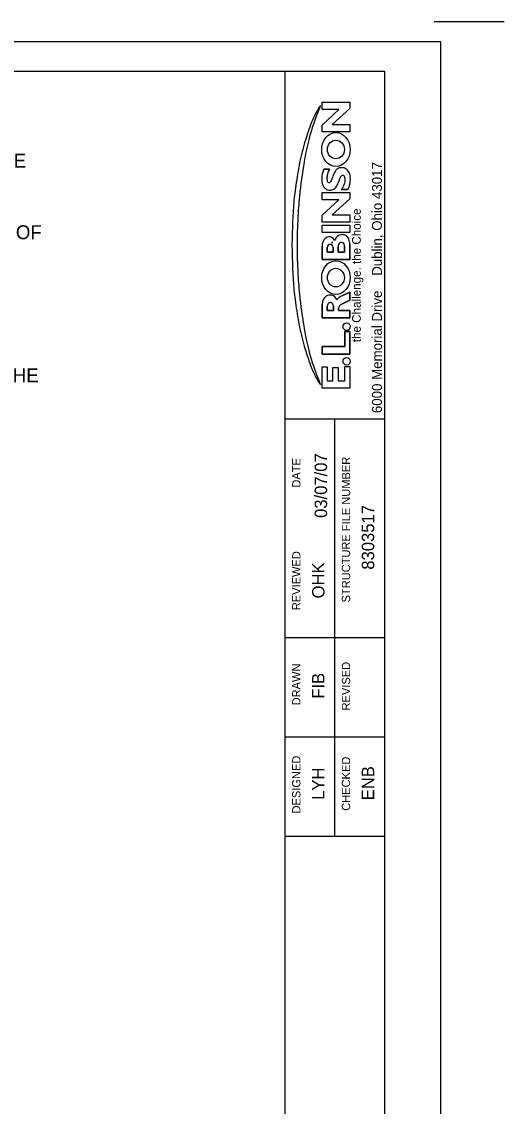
# Model space of a CAD drawing. Extents: x -70.8 to -34.9, y -11.3 to 10.7.
# Drawn here: x -39.72 to -34.87, y -0.19 to 10.73 of the extents above; entities that cross this region are included whole.
import ezdxf

# ---------------------------------------------------------------- set-up
doc = ezdxf.new("R2010")
doc.units = 0
for name, color, linetype in [('BR_P_Gen_Text', 7, 'Continuous'), ('Default', 7, 'Continuous'), ('SH_Border', 7, 'Continuous'), ('SH_Cut_Line', 7, 'Continuous'), ('SH_Data', 7, 'Continuous')]:
    doc.layers.add(name, color=color, linetype=linetype)

msp = doc.modelspace()

# ---------------------------------------------------------------- linework, layer by layer
at = {"layer": 'Default'}
for p, q in [((-36.442, 9.035), (-36.504, 9.035)), ((-36.504, 9.035), (-36.442, 9.035)), ((-36.698, 8.332), (-36.698, 8.466)), ((-36.647, 8.452), (-36.647, 8.407)), ((-36.647, 8.407), (-36.647, 8.452)), ((-36.42, 8.482), (-36.42, 8.332)), ((-36.42, 8.332), (-36.698, 8.332)), ((-36.42, 7.922), (-36.501, 7.882)), ((-36.501, 7.882), (-36.42, 7.922)), ((-36.648, 7.861), (-36.648, 7.819)), ((-36.648, 7.819), (-36.648, 7.861)), ((-36.648, 7.819), (-36.585, 7.819)), ((-36.585, 7.819), (-36.648, 7.819)), ((-36.585, 7.819), (-36.585, 7.861)), ((-36.585, 7.861), (-36.585, 7.819))]:
    msp.add_line(p, q, dxfattribs=at)
for points in [[(-36.42, 9.616), (-36.698, 9.616), (-36.698, 9.685), (-36.53, 9.841), (-36.698, 9.841), (-36.698, 9.915), (-36.42, 9.915), (-36.42, 9.851), (-36.597, 9.69), (-36.42, 9.69)], [(-36.42, 8.708), (-36.698, 8.708), (-36.698, 8.777), (-36.53, 8.933), (-36.698, 8.933), (-36.698, 9.007), (-36.42, 9.007), (-36.42, 8.943), (-36.597, 8.782), (-36.42, 8.782)], [(-36.698, 8.604), (-36.698, 8.678), (-36.42, 8.678), (-36.42, 8.604)], [(-36.698, 7.036), (-36.698, 7.251), (-36.647, 7.251), (-36.647, 7.111), (-36.59, 7.111), (-36.59, 7.243), (-36.538, 7.243), (-36.538, 7.111), (-36.471, 7.111), (-36.471, 7.254), (-36.42, 7.254), (-36.42, 7.036)]]:
    msp.add_lwpolyline(points, close=True, dxfattribs=at)
for points in [[(-36.68, 9.242), (-36.625, 9.242), (-36.636, 9.216)], [(-36.636, 9.216), (-36.625, 9.242), (-36.68, 9.242)], [(-36.42, 8.482), (-36.42, 8.332), (-36.698, 8.332), (-36.698, 8.466)], [(-36.698, 8.466), (-36.698, 8.332), (-36.42, 8.332)], [(-36.647, 8.407), (-36.588, 8.407), (-36.588, 8.452)], [(-36.588, 8.452), (-36.588, 8.407), (-36.647, 8.407)], [(-36.537, 8.461), (-36.537, 8.407), (-36.472, 8.407), (-36.472, 8.461)], [(-36.472, 8.461), (-36.472, 8.407), (-36.537, 8.407), (-36.537, 8.461)], [(-36.42, 8.332), (-36.42, 8.482)], [(-36.484, 7.972), (-36.42, 8.003), (-36.42, 7.922)], [(-36.42, 7.922), (-36.42, 8.003), (-36.484, 7.972)], [(-36.533, 7.84), (-36.533, 7.819), (-36.42, 7.819), (-36.42, 7.744), (-36.698, 7.744), (-36.698, 7.819), (-36.698, 7.883)], [(-36.698, 7.883), (-36.698, 7.819), (-36.698, 7.744), (-36.42, 7.744)], [(-36.648, 7.861), (-36.648, 7.819), (-36.585, 7.819), (-36.585, 7.861)], [(-36.42, 7.744), (-36.42, 7.819), (-36.533, 7.819), (-36.533, 7.84)], [(-36.698, 7.38), (-36.698, 7.455), (-36.471, 7.455), (-36.471, 7.607), (-36.42, 7.607), (-36.42, 7.38), (-36.698, 7.38)], [(-36.42, 7.607), (-36.471, 7.607), (-36.471, 7.455), (-36.698, 7.455), (-36.698, 7.38)], [(-36.698, 7.38), (-36.42, 7.38), (-36.42, 7.607)]]:
    msp.add_lwpolyline(points, dxfattribs=at)
for centre, major_axis, ratio, start_param, end_param in [((-35.936, 9.208), (0, 1.141), 0.85, 0.988431, 1.105191), ((-35.936, 9.208), (0, 1.141), 0.85, 0.988431, 1.105191), ((-75.2, 30.983), (0, 49.953), 0.85, 4.274094, 4.276309), ((-75.2, 30.983), (0, 49.953), 0.85, 4.274094, 4.276309), ((-36.488, 9.636), (0, 0.363), 0.85, 0.822588, 0.988431), ((-36.488, 9.636), (0, 0.363), 0.85, 0.822588, 0.988431), ((-35.457, 9.068), (0, 1.685), 0.85, 1.132502, 1.288747), ((-35.457, 9.068), (0, 1.685), 0.85, 1.132502, 1.288747), ((-36.359, 9.459), (0, 0.583), 0.85, 1.105191, 1.165908), ((-36.359, 9.459), (0, 0.583), 0.85, 1.105191, 1.165908), ((-34.383, 8.462), (0, 3.112), 0.85, 1.165908, 1.233316), ((-34.383, 8.462), (0, 3.112), 0.85, 1.165908, 1.233316), ((-33.959, 8.557), (0, 3.52), 0.85, 1.288747, 1.354281), ((-33.959, 8.557), (0, 3.52), 0.85, 1.288747, 1.354281), ((-35.174, 8.811), (0, 2.119), 0.85, 1.243005, 1.347881), ((-35.174, 8.811), (0, 2.119), 0.85, 1.243005, 1.347881), ((-36.56, 9.439), (0, -0.0938), 0.910305, 4.71238898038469, 4.712389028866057), ((-32.74, 8.363), (0, 4.963), 0.85, 1.378198, 1.448475), ((-32.74, 8.363), (0, 4.963), 0.85, 1.378198, 1.448475), ((-33.985, 8.54), (0, 3.544), 0.85, 1.360764, 1.426378), ((-33.985, 8.54), (0, 3.544), 0.85, 1.360764, 1.426378), ((-36.541, 9.143), (0, 0.19), 0.85, 1.320154, 1.737094), ((-36.541, 9.143), (0, 0.19), 0.85, 1.320154, 1.737094), ((-36.528, 9.139), (0, 0.206), 0.85, 1.108668, 1.320154), ((-36.528, 9.139), (0, 0.206), 0.85, 1.108668, 1.320154), ((-36.819, 9.309), (0, 0.176), 0.85, 4.250261, 4.3216), ((-36.819, 9.309), (0, 0.176), 0.85, 4.250261, 4.3216), ((-36.553, 9.151), (0, 0.115), 0.85, 1.297264, 1.456901), ((-36.553, 9.151), (0, 0.115), 0.85, 1.297264, 1.456901), ((-36.487, 9.129), (0, 0.196), 0.85, 1.114999, 1.297264), ((-36.487, 9.129), (0, 0.196), 0.85, 1.114999, 1.297264), ((-36.401, 9.084), (0, 0.238), 0.85, 1.030221, 1.254809), ((-36.401, 9.084), (0, 0.238), 0.85, 1.030221, 1.254809), ((-36.495, 9.15), (0, 0.11), 0.85, 0.486829, 1.030221), ((-36.495, 9.15), (0, 0.11), 0.85, 0.486829, 1.030221), ((-36.56, 9.439), (0, -0.17), 0.841969, 0, 4.84813681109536e-08), ((-36.508, 9.18), (0, 0.0761), 0.85, 0.083326, 0.486829), ((-36.508, 9.18), (0, 0.0761), 0.85, 0.083326, 0.486829), ((-36.503, 9.102), (0, 0.154), 0.85, 6.083659, 6.366511), ((-36.503, 9.102), (0, 0.154), 0.85, 6.083659, 6.366511), ((-36.491, 9.147), (0, 0.0317), 0.85, 0.212074, 0.715581), ((-36.491, 9.147), (0, 0.0317), 0.85, 0.212074, 0.715581), ((-36.492, 9.153), (0, 0.026), 0.85, 5.247627, 6.495259), ((-36.492, 9.153), (0, 0.026), 0.85, 5.247627, 6.495259), ((-36.489, 9.18), (0, 0.0741), 0.85, 5.529173, 6.083659), ((-36.489, 9.18), (0, 0.0741), 0.85, 5.529173, 6.083659), ((-36.509, 9.155), (0, 0.109), 0.85, 4.887723, 5.529173), ((-36.509, 9.155), (0, 0.109), 0.85, 4.887723, 5.529174), ((-36.589, 9.138), (0, 0.205), 0.85, 4.51081, 4.887723), ((-36.589, 9.138), (0, 0.205), 0.85, 4.51081, 4.887723), ((-36.609, 9.13), (0, 0.11), 0.85, 1.737094, 2.325359), ((-36.609, 9.13), (0, 0.11), 0.85, 1.737094, 2.325359), ((-36.556, 9.152), (0, 0.111), 0.85, 1.456901, 1.818883), ((-36.556, 9.152), (0, 0.111), 0.85, 1.456901, 1.818883), ((-36.625, 9.131), (0, 0.0279), 0.85, 1.818883, 2.384672), ((-36.625, 9.131), (0, 0.0279), 0.85, 1.818883, 2.384672), ((-36.63, 9.125), (0, 0.0197), 0.85, 2.384672, 3.137191), ((-36.63, 9.125), (0, 0.0197), 0.85, 2.384672, 3.137191), ((-36.63, 9.133), (0, 0.0276), 0.85, 3.137191, 4.01614), ((-36.63, 9.133), (0, 0.0276), 0.85, 3.137191, 4.01614), ((-36.658, 9.161), (0, 0.071), 0.85, 4.01614, 4.175459), ((-36.658, 9.161), (0, 0.071), 0.85, 4.01614, 4.175459), ((-36.727, 9.209), (0, 0.165), 0.85, 4.175459, 4.396402), ((-36.727, 9.209), (0, 0.165), 0.85, 4.175459, 4.396402), ((-36.652, 9.154), (0, 0.145), 0.85, 3.971659, 4.353371), ((-36.652, 9.154), (0, 0.145), 0.85, 3.971659, 4.353371), ((-35.918, 8.83), (0, 0.778), 0.85, 1.164639, 1.211778), ((-35.918, 8.83), (0, 0.778), 0.85, 1.164639, 1.211778), ((-36.304, 9.025), (0, 0.284), 0.85, 1.063855, 1.164639), ((-36.304, 9.025), (0, 0.284), 0.85, 1.063855, 1.164639), ((-36.492, 9.148), (0, 0.0304), 0.85, 0.715581, 1.063855), ((-36.492, 9.148), (0, 0.0304), 0.85, 0.715581, 1.063855), ((-36.758, 9.252), (0, 0.37), 0.85, 4.172563, 4.251833), ((-36.758, 9.252), (0, 0.37), 0.85, 4.172563, 4.251833), ((-36.554, 9.133), (0, 0.103), 0.85, 4.251833, 4.86616), ((-36.554, 9.133), (0, 0.103), 0.85, 4.251833, 4.86616), ((-36.509, 9.141), (0, 0.0483), 0.85, 4.86616, 5.247627), ((-36.509, 9.141), (0, 0.0483), 0.85, 4.86616, 5.247627), ((-36.547, 9.124), (0, 0.152), 0.85, 4.087438, 4.318356), ((-36.547, 9.124), (0, 0.152), 0.85, 4.087438, 4.318356), ((-36.563, 9.132), (0, 0.173), 0.85, 4.318356, 4.51081), ((-36.563, 9.132), (0, 0.173), 0.85, 4.318356, 4.51081), ((-35.406, 8.718), (0, 1.866), 0.85, 1.391456, 1.496401), ((-35.406, 8.718), (0, 1.866), 0.85, 1.391456, 1.496401), ((-31.142, 8.297), (0, 6.84), 0.85, 1.472392, 1.505619), ((-31.142, 8.297), (0, 6.84), 0.85, 1.472392, 1.505619), ((-36.629, 9.107), (0, 0.0764), 0.85, 2.325359, 2.878408), ((-36.629, 9.107), (0, 0.0764), 0.85, 2.325359, 2.878408), ((-36.621, 9.142), (0, 0.113), 0.85, 2.878408, 3.55749), ((-36.621, 9.142), (0, 0.113), 0.85, 2.878408, 3.55749), ((-36.608, 9.106), (0, 0.0738), 0.85, 3.55749, 3.971659), ((-36.608, 9.106), (0, 0.0738), 0.85, 3.55749, 3.971659), ((-36.681, 9.198), (0, 0.265), 0.85, 4.050165, 4.172563), ((-36.681, 9.198), (0, 0.265), 0.85, 4.050165, 4.172563), ((-35.204, 8.616), (0, 2.111), 0.85, 1.456986, 1.558686), ((-35.204, 8.616), (0, 2.111), 0.85, 1.456986, 1.558686), ((-33.598, 8.485), (0, 3.944), 0.85, 1.505619, 1.553601), ((-33.598, 8.485), (0, 3.944), 0.85, 1.505619, 1.553601), ((-33.396, 8.423), (0, 4.243), 0.85, 1.519271, 1.558345), ((-33.396, 8.423), (0, 4.243), 0.85, 1.519271, 1.558345), ((-35.049, 8.515), (0, 2.237), 0.85, 1.553601, 1.587991), ((-35.049, 8.515), (0, 2.237), 0.85, 1.553601, 1.587991), ((-36.626, 8.476), (0, 0.0833), 0.85, 0.473795, 1.194239), ((-36.626, 8.476), (0, 0.0833), 0.85, 0.473795, 1.194239), ((-36.626, 8.476), (0, 0.0833), 0.85, 0.473795, 1.194239), ((-36.629, 8.49), (0, 0.0696), 0.85, 5.943917, 6.808987), ((-36.629, 8.49), (0, 0.0696), 0.85, 5.943917, 6.808987), ((-36.629, 8.49), (0, 0.0696), 0.85, 5.943917, 6.808987), ((-36.631, 8.482), (0, 0.0776), 0.85, 5.231996, 5.947796), ((-36.631, 8.482), (0, 0.0776), 0.85, 5.231996, 5.947796), ((-36.631, 8.482), (0, 0.0776), 0.85, 5.231996, 5.947795), ((-36.501, 8.492), (0, 0.0906), 0.85, 0.462144, 1.247207), ((-36.501, 8.492), (0, 0.0906), 0.85, 0.462144, 1.247207), ((-36.501, 8.492), (0, 0.0906), 0.85, 0.462144, 1.247207), ((-36.5, 8.484), (0, 0.0982), 0.85, 6.14188, 6.715345), ((-36.5, 8.484), (0, 0.0982), 0.85, 6.14188, 6.715345), ((-36.5, 8.484), (0, 0.0982), 0.85, 6.14188, 6.715345), ((-36.496, 8.493), (0, 0.0885), 0.85, 5.535543, 6.182102), ((-36.496, 8.493), (0, 0.0885), 0.85, 5.535543, 6.182102), ((-36.496, 8.493), (0, 0.0885), 0.85, 5.535543, 6.182102), ((-36.491, 8.497), (0, 0.0818), 0.85, 4.885157, 5.560215), ((-36.491, 8.497), (0, 0.0818), 0.85, 4.885157, 5.560215), ((-36.491, 8.497), (0, 0.0818), 0.85, 4.885157, 5.560215), ((-33.396, 8.529), (0, 4.243), 0.85, 1.583248, 1.622322), ((-33.396, 8.529), (0, 4.243), 0.85, 1.583248, 1.622322), ((-35.049, 8.438), (0, 2.237), 0.85, 1.553601, 1.587991), ((-35.049, 8.438), (0, 2.237), 0.85, 1.553601, 1.587991), ((-36.593, 8.465), (0, 0.124), 0.85, 1.228703, 1.558605), ((-36.593, 8.465), (0, 0.124), 0.85, 1.228703, 1.558605), ((-36.593, 8.465), (0, 0.124), 0.85, 1.228703, 1.558605), ((-36.619, 8.45), (0, 0.0337), 0.85, 6.249041, 7.784024), ((-36.619, 8.45), (0, 0.0337), 0.85, 6.249041, 7.784024), ((-36.617, 8.45), (0, 0.0337), 0.85, 4.782347, 6.317329), ((-36.617, 8.45), (0, 0.0337), 0.85, 4.782347, 6.317329), ((-36.503, 8.463), (0, 0.0402), 0.85, 0.503186, 1.629765), ((-36.503, 8.463), (0, 0.0402), 0.85, 0.503186, 1.629765), ((-36.505, 8.467), (0, 0.0358), 0.85, 6.277029, 6.794667), ((-36.505, 8.467), (0, 0.0358), 0.85, 6.277029, 6.794667), ((-36.504, 8.467), (0, 0.0358), 0.85, 5.771704, 6.289341), ((-36.504, 8.467), (0, 0.0358), 0.85, 5.771704, 6.289341), ((-36.506, 8.463), (0, 0.0402), 0.85, 4.65342, 5.779999), ((-36.506, 8.463), (0, 0.0402), 0.85, 4.65342, 5.779999), ((-36.591, 8.474), (0, 0.202), 0.85, 4.750784, 4.89449), ((-36.591, 8.474), (0, 0.202), 0.85, 4.750784, 4.89449), ((-36.591, 8.474), (0, 0.202), 0.85, 4.750784, 4.89449), ((-35.204, 8.336), (0, 2.111), 0.85, 1.582906, 1.684607), ((-35.204, 8.336), (0, 2.111), 0.85, 1.582906, 1.684607), ((-33.598, 8.467), (0, 3.944), 0.85, 1.587991, 1.635974), ((-33.598, 8.467), (0, 3.944), 0.85, 1.587991, 1.635974), ((-31.142, 8.656), (0, 6.84), 0.85, 1.635974, 1.669201), ((-31.142, 8.656), (0, 6.84), 0.85, 1.635974, 1.669201), ((-35.406, 8.235), (0, 1.866), 0.85, 1.645192, 1.750137), ((-35.406, 8.235), (0, 1.866), 0.85, 1.645192, 1.750137), ((-36.56, 8.149), (0, -0.0938), 0.910305, 4.71238898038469, 4.712389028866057), ((-32.74, 8.589), (0, 4.963), 0.85, 1.693118, 1.763395), ((-32.74, 8.589), (0, 4.963), 0.85, 1.693118, 1.763395), ((-36.617, 7.873), (0, 0.1), 0.85, 6.102437, 6.781247), ((-36.617, 7.873), (0, 0.1), 0.85, 6.102437, 6.781247), ((-36.618, 7.886), (0, 0.0881), 0.85, 5.152888, 6.061538), ((-36.618, 7.886), (0, 0.0881), 0.85, 5.152888, 6.061538), ((-36.56, 8.149), (0, -0.17), 0.841969, 0, 4.84813681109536e-08), ((-36.393, 7.675), (0, 0.316), 0.85, 0.346308, 0.520291), ((-36.393, 7.675), (0, 0.316), 0.85, 0.346308, 0.520291), ((-33.985, 8.412), (0, 3.544), 0.85, 1.715214, 1.780828), ((-33.985, 8.412), (0, 3.544), 0.85, 1.715214, 1.780828), ((-36.622, 7.882), (0, 0.0895), 0.85, 0.482355, 1.561069), ((-36.622, 7.882), (0, 0.0895), 0.85, 0.482355, 1.561069), ((-36.608, 7.858), (0, 0.0467), 0.85, 1.002734, 1.50285), ((-36.608, 7.858), (0, 0.0467), 0.85, 1.002734, 1.50285), ((-36.608, 7.858), (0, 0.0467), 0.85, 1.002734, 1.50285), ((-36.617, 7.861), (0, 0.0365), 0.85, 6.259044, 7.205975), ((-36.617, 7.861), (0, 0.0365), 0.85, 6.259044, 7.205975), ((-36.617, 7.861), (0, 0.0365), 0.85, 6.259044, 7.205975), ((-36.615, 7.861), (0, 0.0365), 0.85, 5.360396, 6.307326), ((-36.615, 7.861), (0, 0.0365), 0.85, 5.360396, 6.307326), ((-36.615, 7.861), (0, 0.0365), 0.85, 5.360396, 6.307326), ((-36.624, 7.858), (0, 0.0467), 0.85, 4.780335, 5.280452), ((-36.624, 7.858), (0, 0.0467), 0.85, 4.780335, 5.280452), ((-36.624, 7.858), (0, 0.0467), 0.85, 4.780335, 5.280452), ((-36.501, 7.887), (0, 0.069), 0.85, 0.463729, 1.012038), ((-36.501, 7.887), (0, 0.069), 0.85, 0.463729, 1.012038), ((-36.484, 7.821), (0, 0.0643), 0.85, 0.32473, 0.965239), ((-36.484, 7.821), (0, 0.0643), 0.85, 0.32473, 0.965239), ((-36.507, 7.841), (0, 0.0303), 0.85, 0.984544, 1.600686), ((-36.507, 7.841), (0, 0.0303), 0.85, 0.984544, 1.600686), ((-35.174, 8.142), (0, 2.119), 0.85, 1.793712, 1.898588), ((-35.174, 8.142), (0, 2.119), 0.85, 1.793712, 1.898588), ((-36.452, 7.656), (0, -0.0377), 0.965476, 4.71238898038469, 4.712389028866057), ((-33.959, 8.396), (0, 3.52), 0.85, 1.787312, 1.852845), ((-33.959, 8.396), (0, 3.52), 0.85, 1.787312, 1.852845), ((-34.383, 8.49), (0, 3.112), 0.85, 1.908276, 1.975684), ((-34.383, 8.49), (0, 3.112), 0.85, 1.908276, 1.975684), ((-35.457, 7.885), (0, 1.685), 0.85, 1.852845, 2.009091), ((-35.457, 7.885), (0, 1.685), 0.85, 1.852845, 2.009091), ((-36.359, 7.494), (0, 0.583), 0.85, 1.975684, 2.036401), ((-36.359, 7.494), (0, 0.583), 0.85, 1.975684, 2.036401), ((-35.936, 7.744), (0, 1.141), 0.85, 2.036401, 2.153161), ((-35.936, 7.744), (0, 1.141), 0.85, 2.036401, 2.153161), ((-36.452, 7.307), (0, -0.0377), 0.965476, 4.71238898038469, 4.712389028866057), ((-75.2, -14.03), (0, 49.953), 0.85, 5.148469, 5.150684), ((-75.2, -14.03), (0, 49.953), 0.85, 5.148469, 5.150684), ((-36.488, 7.316), (0, 0.363), 0.85, 2.153161, 2.319004), ((-36.488, 7.316), (0, 0.363), 0.85, 2.153161, 2.319004)]:
    msp.add_ellipse(centre, major_axis=major_axis, ratio=ratio, start_param=start_param, end_param=end_param, dxfattribs=at)
for centre, major_axis, ratio in [((-36.56, 9.439), (0, -0.17), 0.841969), ((-36.56, 9.439), (0, -0.17), 0.841969), ((-36.56, 9.439), (0, -0.0938), 0.910305), ((-36.56, 9.439), (0, -0.0938), 0.910305), ((-36.56, 8.149), (0, -0.17), 0.841969), ((-36.56, 8.149), (0, -0.17), 0.841969), ((-36.56, 8.149), (0, -0.0938), 0.910305), ((-36.56, 8.149), (0, -0.0938), 0.910305), ((-36.452, 7.656), (0, -0.0377), 0.965476), ((-36.452, 7.307), (0, -0.0377), 0.965476), ((-36.452, 7.307), (0, -0.0377), 0.965476)]:
    msp.add_ellipse(centre, major_axis=major_axis, ratio=ratio, dxfattribs=at)
at = {"layer": 'SH_Border'}
for p, q in [((-37.071, -10.774), (-37.071, 10.226)), ((-37.071, 6.726), (-36.071, 6.726)), ((-36.571, 2.526), (-36.571, 6.726)), ((-37.071, 4.526), (-36.071, 4.526)), ((-37.071, 3.526), (-36.071, 3.526)), ((-37.071, 2.526), (-36.071, 2.526))]:
    msp.add_line(p, q, dxfattribs=at)
msp.add_lwpolyline([(-67.571, 10.226), (-36.071, 10.226), (-36.071, -10.774), (-67.571, -10.774)], close=True, dxfattribs=at)
at = {"layer": 'SH_Cut_Line'}
msp.add_line((-35.571, 10.726), (-34.866, 10.726), dxfattribs=at)
msp.add_lwpolyline([(-35.509, -11.124), (-69.509, -11.124), (-69.509, 10.526), (-35.509, 10.526)], close=True, dxfattribs=at)

# ---------------------------------------------------------------- texts
at = {"layer": 'BR_P_Gen_Text'}
for s, p in [('WITH CLEAN WATER AND ALLOW TO DRY TO A DAMP CONDITION BEFORE ', (-46.479, 9.256)), ('SUBSTRUCTURE CONCRETE REMOVAL: REMOVE CONCRETE BY MEANS OF ', (-46.479, 8.536)), ('USE HAMMERS NOT EXCEEDING 90 POUNDS UPON THE APPROVAL OF THE ', (-46.479, 7.096))]:
    msp.add_text(s, height=0.14, dxfattribs=at).set_placement(p)
at = {"layer": 'Default'}
for s, height, p in [('6000 Memorial Drive    Dublin, Ohio 43017', 0.1, (-36.097, 6.785)), ('the Challenge. the Choice', 0.0875, (-36.31, 7.499))]:
    msp.add_text(s, height=height, rotation=90, dxfattribs=at).set_placement(p)
at = {"layer": 'SH_Data'}
for s, height, p in [('.', 0.125, (-36.588, 8.479)), ("'", 0.125, (-36.254, 8.479)), ('03/07/07', 0.125, (-36.649, 5.73)), ('STRUCTURE FILE NUMBER', 0.0833, (-36.417, 4.879)), ('DATE', 0.0833, (-36.917, 6.035)), ('8303517', 0.125, (-36.175, 5.209)), ('REVIEWED', 0.0833, (-36.917, 4.801)), ('OHK', 0.125, (-36.675, 4.92)), ('REVISED', 0.0833, (-36.417, 3.792)), ('DRAWN', 0.0833, (-36.917, 3.843)), ('FIB', 0.125, (-36.675, 3.91)), ('DESIGNED', 0.0833, (-36.917, 2.755)), ('CHECKED', 0.0833, (-36.417, 2.782)), ('LYH', 0.125, (-36.675, 2.892)), ('ENB', 0.125, (-36.175, 2.888))]:
    msp.add_text(s, height=height, rotation=90, dxfattribs=at).set_placement(p)

doc.saveas('drawing.dxf')
